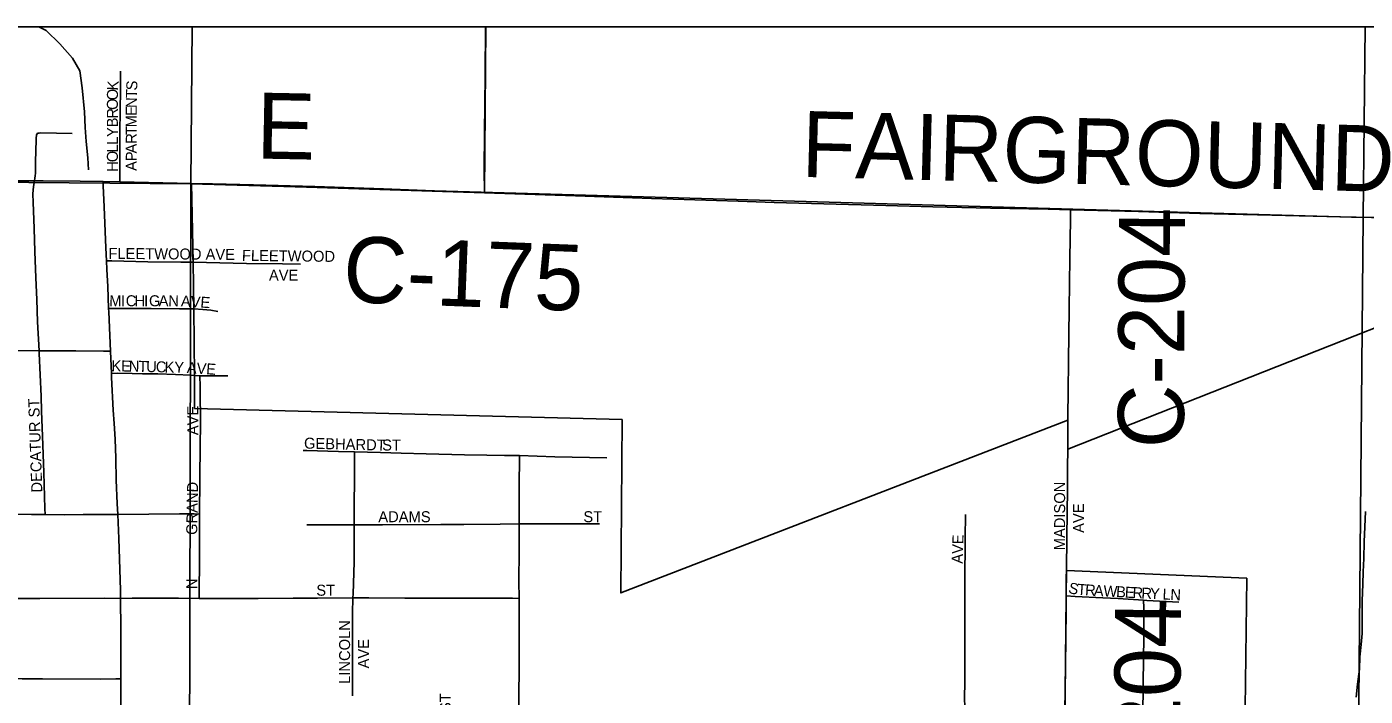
# Model space of a CAD drawing. Extents: x -9.1 to 34, y -3.1 to 22.
# Drawn here: x 6.099 to 7.252, y 20.324 to 20.9 of the extents above; entities that cross this region are included whole.
import ezdxf

# ---------------------------------------------------------------- set-up
doc = ezdxf.new("R2010")
doc.units = 0
for name, color, linetype in [('GM_X_City_Street', 7, 'Continuous'), ('GM_X_City_Street_Text', 7, 'Continuous'), ('GM_X_Corporation', 7, 'Continuous'), ('GM_X_County_Road', 7, 'Continuous'), ('GM_X_County_Road_Text', 7, 'Continuous'), ('GM_X_Minor_River', 7, 'Continuous'), ('GM_X_Section', 7, 'Continuous'), ('GM_X_Township_Subdivision', 7, 'Continuous'), ('GM_X_Township_Subdivision_Text', 7, 'Continuous')]:
    doc.layers.add(name, color=color, linetype=linetype)

msp = doc.modelspace()

# ---------------------------------------------------------------- linework, layer by layer
at = {"layer": 'GM_X_City_Street'}
for points in [[(6.1792, 20.7664), (6.1791, 20.7726), (6.179, 20.7879), (6.1792, 20.8001), (6.1792, 20.8093), (6.1796, 20.8461), (6.1796, 20.8584), (6.1796, 20.8617)], [(6.1055, 20.7674), (6.106, 20.7697), (6.1063, 20.7716), (6.1064, 20.7739), (6.1065, 20.7836), (6.1069, 20.8026), (6.107, 20.8046), (6.1072, 20.8061), (6.1073, 20.8068), (6.1076, 20.8075), (6.1079, 20.8079), (6.1082, 20.8083), (6.1086, 20.8085), (6.1096, 20.8085), (6.1111, 20.8086), (6.138, 20.8082)], [(6.0535, 20.768), (6.0861, 20.7674), (6.0951, 20.7674), (6.1055, 20.7674)], [(6.1095, 20.621), (6.1083, 20.6459), (6.1077, 20.6652), (6.1068, 20.6838), (6.106, 20.7064), (6.1053, 20.7263), (6.1045, 20.749), (6.1042, 20.7559), (6.1044, 20.7597), (6.1046, 20.7621), (6.1049, 20.7641), (6.1055, 20.7674)], [(6.1055, 20.7674), (6.113, 20.7673), (6.145, 20.7671), (6.1646, 20.7667)], [(6.1646, 20.7667), (6.1792, 20.7664)], [(6.1676, 20.6985), (6.1671, 20.7097), (6.1655, 20.7449), (6.1647, 20.7632), (6.1646, 20.7667)], [(6.1792, 20.7664), (6.2408, 20.7651)], [(6.1694, 20.6574), (6.1687, 20.6763), (6.1679, 20.6911), (6.1676, 20.6985)], [(6.1676, 20.6985), (6.1721, 20.6984), (6.2032, 20.6977), (6.2315, 20.6973), (6.2421, 20.6973)], [(6.1694, 20.6574), (6.1754, 20.6575), (6.1875, 20.6575), (6.206, 20.6574), (6.2306, 20.6573), (6.2429, 20.6571)], [(6.1711, 20.6206), (6.1705, 20.6341), (6.1695, 20.6545), (6.1694, 20.6574)], [(6.0476, 20.6216), (6.0834, 20.6212), (6.1095, 20.621)], [(6.1147, 20.48), (6.1146, 20.4853), (6.1135, 20.5164), (6.1126, 20.5475), (6.1116, 20.569), (6.1112, 20.582), (6.1096, 20.6187), (6.1095, 20.621)], [(6.1095, 20.621), (6.1237, 20.6209), (6.1411, 20.6209), (6.165, 20.6206), (6.1711, 20.6206)], [(6.1719, 20.6016), (6.1711, 20.6206)], [(6.1719, 20.6016), (6.177, 20.6017), (6.1897, 20.6015), (6.1987, 20.6013), (6.2117, 20.6011), (6.227, 20.6007), (6.24, 20.6001), (6.2481, 20.5995)], [(6.1773, 20.4802), (6.1769, 20.4895), (6.176, 20.5098), (6.1756, 20.5286), (6.175, 20.5451), (6.1742, 20.5585), (6.1734, 20.5699), (6.172, 20.598), (6.1719, 20.6016)], [(6.2478, 20.4805), (6.2483, 20.5404), (6.2485, 20.5571), (6.2485, 20.5715)], [(6.3369, 20.5352), (6.34, 20.5351), (6.3673, 20.5343), (6.3811, 20.534)], [(6.381, 20.4713), (6.3809, 20.4855), (6.3809, 20.4948), (6.3811, 20.5041), (6.3811, 20.5191), (6.3811, 20.5309), (6.3811, 20.534)], [(6.3811, 20.534), (6.4037, 20.5335), (6.4213, 20.5329), (6.4428, 20.5324), (6.4758, 20.5315), (6.4951, 20.5312), (6.5105, 20.531), (6.5232, 20.5309)], [(6.523, 20.472), (6.523, 20.5068), (6.5232, 20.5272), (6.5232, 20.5309)], [(6.5232, 20.5309), (6.5537, 20.5297), (6.5985, 20.5288)], [(6.9943, 20.432), (6.9948, 20.461), (6.9953, 20.5018), (6.9952, 20.5207), (6.9954, 20.5365)], [(6.054, 20.4803), (6.0561, 20.4803), (6.0706, 20.4803), (6.1031, 20.4801), (6.1147, 20.48)], [(6.1147, 20.48), (6.1311, 20.4799), (6.1474, 20.48), (6.1773, 20.4802)], [(6.1773, 20.4802), (6.1777, 20.4802), (6.2305, 20.4807), (6.243, 20.4806), (6.2478, 20.4805)], [(6.1797, 20.4079), (6.1797, 20.415), (6.1782, 20.4595), (6.1773, 20.4802)], [(6.2474, 20.4079), (6.2475, 20.4146), (6.2476, 20.439), (6.2476, 20.4606), (6.2478, 20.4791), (6.2478, 20.4805)], [(6.9054, 20.1425), (6.9054, 20.1469), (6.9055, 20.1758), (6.9055, 20.1928), (6.906, 20.2298), (6.9063, 20.2633), (6.9065, 20.2929), (6.9066, 20.3019), (6.9067, 20.3132), (6.9066, 20.3233), (6.9067, 20.3345), (6.9068, 20.3482), (6.9068, 20.3807), (6.9067, 20.408), (6.9067, 20.4171), (6.9069, 20.4348), (6.907, 20.4466), (6.9071, 20.4599), (6.9074, 20.4801)], [(6.34, 20.4712), (6.3663, 20.4712), (6.381, 20.4713)], [(6.3798, 20.4084), (6.3799, 20.4118), (6.3809, 20.439), (6.3809, 20.4484), (6.381, 20.4669), (6.381, 20.4713)], [(6.381, 20.4713), (6.4052, 20.4712), (6.4556, 20.4714), (6.4754, 20.4714), (6.5067, 20.4717), (6.523, 20.472)], [(6.5229, 20.4078), (6.5228, 20.4226), (6.523, 20.4485), (6.523, 20.4603), (6.523, 20.472)], [(6.523, 20.472), (6.5574, 20.472), (6.5891, 20.4721), (6.5922, 20.4721)], [(6.0485, 20.4078), (6.0713, 20.4077), (6.1102, 20.4079), (6.1661, 20.408), (6.1797, 20.4079)], [(6.1797, 20.4079), (6.1898, 20.408), (6.2297, 20.408), (6.2474, 20.4079)], [(6.1798, 20.3386), (6.1798, 20.3534), (6.1798, 20.3811), (6.1797, 20.4079)], [(6.2474, 20.4079), (6.2572, 20.4079), (6.277, 20.4079), (6.2982, 20.4079), (6.3285, 20.4081), (6.3493, 20.4081), (6.3798, 20.4084)], [(6.3796, 20.3239), (6.3796, 20.3289), (6.3796, 20.3345), (6.3796, 20.3473), (6.3795, 20.3749), (6.3795, 20.3952), (6.3798, 20.4084)], [(6.3798, 20.4084), (6.3935, 20.4085), (6.4244, 20.4082), (6.4583, 20.4081), (6.4999, 20.4081), (6.5108, 20.4081), (6.5173, 20.408), (6.5229, 20.4078)], [(6.5221, 20.2107), (6.5221, 20.2204), (6.5222, 20.2311), (6.5222, 20.2391), (6.5222, 20.2491), (6.5222, 20.2561), (6.5222, 20.2651), (6.5222, 20.2735), (6.5223, 20.2825), (6.5224, 20.3021), (6.5227, 20.318), (6.5227, 20.3282), (6.5229, 20.3435), (6.5229, 20.3643), (6.523, 20.3809), (6.5229, 20.4078)], [(5.7908, 20.3383), (5.7974, 20.3383), (5.8144, 20.3383), (5.8431, 20.3383), (5.8688, 20.3383), (5.8899, 20.3383), (5.9215, 20.3385), (5.9461, 20.3387), (5.9896, 20.3389), (6.0176, 20.3389), (6.0361, 20.3389), (6.062, 20.339), (6.0803, 20.3389), (6.0951, 20.3387), (6.1124, 20.3387), (6.162, 20.3385), (6.1756, 20.3386), (6.1798, 20.3386)], [(6.1798, 20.2702), (6.1798, 20.323), (6.1798, 20.3386)]]:
    msp.add_lwpolyline(points, dxfattribs=at)
at = {"layer": 'GM_X_Corporation'}
msp.add_line((6.4943, 20.9), (5.0413, 20.9), dxfattribs=at)
for points in [[(7.5132, 20.7408), (6.9954, 20.5365), (6.9955, 20.5612), (6.6105, 20.4126), (6.6117, 20.5619), (6.2434, 20.5714), (6.2433, 20.5999), (6.2429, 20.6571), (6.2421, 20.6973), (6.2408, 20.7651), (6.4931, 20.757), (6.4943, 20.9)], [(6.9919, 20.1881), (6.994, 20.41), (6.9943, 20.432), (7.1496, 20.4253), (7.1476, 20.2687)]]:
    msp.add_lwpolyline(points, dxfattribs=at)
at = {"layer": 'GM_X_County_Road'}
for points in [[(6.4931, 20.757), (6.493, 20.7772), (6.4931, 20.8083), (6.4938, 20.858), (6.4941, 20.9)], [(6.2408, 20.7651), (6.2588, 20.7647)], [(6.2588, 20.7647), (6.2943, 20.7638), (6.3471, 20.7625), (6.4061, 20.7604), (6.4495, 20.7587), (6.4931, 20.757)], [(6.4931, 20.757), (6.5716, 20.7544), (6.6369, 20.7521), (6.7115, 20.7498), (6.7425, 20.7487), (6.8388, 20.7461), (6.8792, 20.745), (6.9289, 20.7439), (6.9787, 20.7429), (6.9979, 20.7424)], [(6.9955, 20.5612), (6.9956, 20.5653), (6.9959, 20.5858), (6.9962, 20.6128), (6.9966, 20.6572), (6.9974, 20.7007), (6.9978, 20.7338), (6.9979, 20.7424)], [(6.9979, 20.7424), (7.0563, 20.7409), (7.1091, 20.7392), (7.1713, 20.7379), (7.2303, 20.7363), (7.2707, 20.7355)], [(6.9954, 20.5365), (6.9955, 20.5461), (6.9955, 20.5593), (6.9955, 20.5612)], [(6.994, 20.41), (6.994, 20.4137), (6.9942, 20.4263), (6.9943, 20.432)], [(6.9917, 20.1921), (6.9917, 20.2031), (6.9919, 20.2169), (6.9922, 20.2351), (6.9928, 20.2578), (6.9927, 20.2796), (6.9928, 20.3016), (6.9932, 20.3263), (6.9935, 20.3506), (6.9938, 20.3727), (6.994, 20.3981), (6.994, 20.41)]]:
    msp.add_lwpolyline(points, dxfattribs=at)
at = {"layer": 'GM_X_Minor_River'}
for points in [[(6.1094, 20.9), (6.1155, 20.8967), (6.1275, 20.8852), (6.1383, 20.8729), (6.1446, 20.8622), (6.1467, 20.8474), (6.1487, 20.8269), (6.1492, 20.8133), (6.1502, 20.8011), (6.1515, 20.7871), (6.1521, 20.7769)], [(7.2438, 20.3228), (7.245, 20.3342), (7.2466, 20.3471), (7.247, 20.3577), (7.2482, 20.3683), (7.249, 20.3777), (7.2491, 20.4058), (7.2495, 20.4202), (7.2499, 20.4308), (7.2504, 20.4422), (7.2508, 20.4566), (7.2512, 20.4695), (7.252, 20.4827)]]:
    msp.add_lwpolyline(points, dxfattribs=at)
at = {"layer": 'GM_X_Section'}
for p, q in [((6.2414, 20.9), (5.2292, 20.9)), ((7.2516, 20.9), (6.2414, 20.9)), ((8.2709, 20.9), (7.2516, 20.9))]:
    msp.add_line(p, q, dxfattribs=at)
for points in [[(5.2292, 20.9), (5.2279, 20.7732), (6.2403, 20.7648), (6.2414, 20.9)], [(6.2414, 20.9), (6.2403, 20.7648), (7.2498, 20.7358), (7.2516, 20.9)], [(7.2516, 20.9), (7.2498, 20.7358), (8.2683, 20.7561), (8.2692, 20.7856), (8.2709, 20.9)]]:
    msp.add_lwpolyline(points, dxfattribs=at)
for points in [[(5.2279, 20.7732), (6.2403, 20.7648), (6.2379, 19.7608), (5.226, 19.7723)], [(7.2498, 20.7358), (7.2408, 19.7107), (6.2379, 19.7608), (6.2403, 20.7648)], [(8.2683, 20.7561), (8.2596, 19.7802), (7.2408, 19.7107), (7.2498, 20.7358)]]:
    msp.add_lwpolyline(points, close=True, dxfattribs=at)
at = {"layer": 'GM_X_Township_Subdivision'}
for points in [[(6.2421, 20.6973), (6.2883, 20.6962), (6.3193, 20.6958), (6.3348, 20.6956)], [(6.2429, 20.6571), (6.2507, 20.6567), (6.2574, 20.6559), (6.2634, 20.655)], [(6.2481, 20.5995), (6.2545, 20.5995), (6.2636, 20.5996), (6.272, 20.5996)], [(6.2485, 20.5715), (6.2484, 20.5746), (6.2483, 20.5904), (6.2481, 20.5995)], [(6.994, 20.41), (7.0018, 20.4096), (7.0256, 20.4084), (7.0388, 20.4077), (7.0606, 20.4063)], [(7.059, 20.2527), (7.0594, 20.2802), (7.06, 20.308), (7.0607, 20.3575), (7.061, 20.3727), (7.0611, 20.3845), (7.061, 20.3936), (7.0609, 20.3997), (7.0606, 20.4063)], [(7.0606, 20.4063), (7.0635, 20.4061), (7.0912, 20.4047)]]:
    msp.add_lwpolyline(points, dxfattribs=at)

# ---------------------------------------------------------------- texts
at = {"layer": 'GM_X_City_Street_Text'}
for s, rotation, p in [('K', 86.3909, (6.1775, 20.8449)), ('O', 89.4972, (6.1774, 20.8367)), ('T', 88.8253, (6.1937, 20.8384)), ('S', 86.9929, (6.1939, 20.845)), ('O', 89.9928, (6.1774, 20.8284)), ('N', 89.5847, (6.1937, 20.8301)), ('E', 89.9727, (6.1937, 20.8234)), ('R', 89.9703, (6.1774, 20.8209)), ('B', 89.9757, (6.1774, 20.8134)), ('M', 90, (6.1937, 20.8134)), ('Y', 89.9928, (6.1774, 20.8051)), ('T', 90, (6.1937, 20.8068)), ('R', 90, (6.1937, 20.7993)), ('L', 89.9707, (6.1774, 20.7984)), ('L', 89.9727, (6.1774, 20.7918)), ('A', 90, (6.1937, 20.7909)), ('O', 89.9928, (6.1774, 20.7834)), ('P', 90, (6.1937, 20.7843)), ('A', 90, (6.1937, 20.7759)), ('H', 89.9781, (6.1774, 20.7751)), ('FLEETWOOD AVE', 359.5061, (6.1692, 20.7002)), ('M', 359.9818, (6.17, 20.6594)), ('I', 359.985, (6.18, 20.6594)), ('C', 359.9757, (6.1842, 20.6594)), ('H', 359.9813, (6.1917, 20.6594)), ('I', 0, (6.2, 20.6594)), ('G', 359.9781, (6.2042, 20.6594)), ('A', 359.9929, (6.2125, 20.6594)), ('N', 359.7377, (6.2208, 20.6594)), ('A', 356.8287, (6.2315, 20.6593)), ('V', 356.3037, (6.2398, 20.6588)), ('E', 356.3095, (6.2482, 20.6583)), ('K', 358.6012, (6.1717, 20.6035)), ('E', 358.5795, (6.1801, 20.6033)), ('N', 358.5966, (6.1867, 20.6032)), ('T', 358.5795, (6.195, 20.603)), ('U', 358.5966, (6.2017, 20.6028)), ('C', 358.5916, (6.21, 20.6026)), ('K', 358.5966, (6.2175, 20.6024)), ('Y', 358.5794, (6.2259, 20.6022)), ('A', 356.9826, (6.2366, 20.6019)), ('V', 355.7991, (6.2449, 20.6015)), ('E', 355.7878, (6.2532, 20.6009)), ('DECATUR ST', 92.0203, (6.1124, 20.4992)), ('AVE', 90, (6.2466, 20.5484)), ('GEBHARDT', 358.4932, (6.3376, 20.5369)), ('ST', 0, (6.405, 20.5352)), ('GRAND', 89.0478, (6.2457, 20.4625)), ('MADISON', 90, (6.9932, 20.4493)), ('AVE', 90, (7.0095, 20.4643)), ('ADAMS', 0, (6.4017, 20.4735)), ('ST', 0, (6.5783, 20.4735)), ('E', 88.323, (6.9055, 20.4544)), ('V', 87.9324, (6.9052, 20.446)), ('A', 87.9234, (6.9049, 20.4377)), ('N', 90, (6.2457, 20.4159)), ('ST', 0, (6.3483, 20.4102)), ('LINCOLN', 90, (6.3774, 20.3343)), ('AVE', 90, (6.3937, 20.3476)), ('ST', 90, (6.4641, 20.3101))]:
    msp.add_text(s, height=0.00947, rotation=rotation, dxfattribs=at).set_placement(p)
at = {"layer": 'GM_X_County_Road_Text'}
for s, height, rotation, p in [('E', 0.0568, 358.8731, (6.2963, 20.7866)), ('FAIRGROUND', 0.05682, 358.5316, (6.7657, 20.7708)), ('C-204', 0.05682, 89.724, (7.0954, 20.5371)), ('C-175', 0.05682, 357.7932, (6.3706, 20.6632)), ('C-204', 0.05682, 89.4594, (7.0912, 20.2003))]:
    msp.add_text(s, height=height, rotation=rotation, dxfattribs=at).set_placement(p)
at = {"layer": 'GM_X_Township_Subdivision_Text'}
for s, rotation, p in [('FLEETWOOD', 359.3332, (6.2842, 20.6985)), ('AVE', 0, (6.3075, 20.6814)), ('S', 348.2239, (6.9955, 20.4126)), ('T', 355.7348, (7.0034, 20.4111)), ('R', 356.6891, (7.0102, 20.4106)), ('A', 356.784, (7.0177, 20.4101)), ('W', 356.7835, (7.026, 20.4097)), ('B', 356.7966, (7.0369, 20.4091)), ('E', 356.802, (7.0444, 20.4086)), ('R', 356.7932, (7.051, 20.4083)), ('R', 357.76, (7.0587, 20.4078)), ('Y', 357.0263, (7.0661, 20.4076)), ('L', 356.993, (7.0769, 20.407)), ('N', 356.9826, (7.0836, 20.4066))]:
    msp.add_text(s, height=0.00947, rotation=rotation, dxfattribs=at).set_placement(p)

doc.saveas('drawing.dxf')
